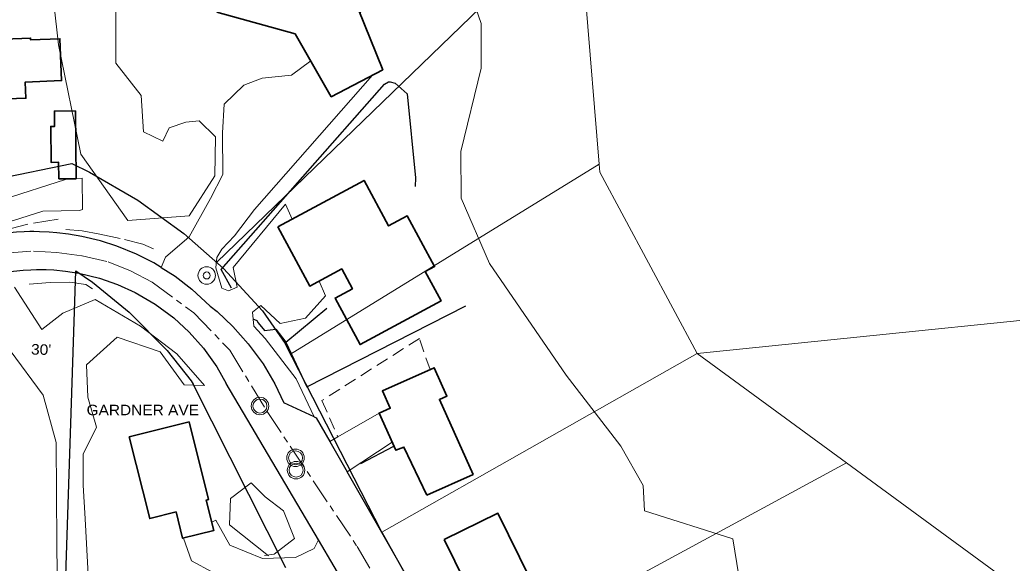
# Model space of a CAD drawing. Extents: x -861682 to -858969, y -1797841 to -1795153.
# Drawn here: x -860350 to -859783, y -1795814 to -1795504 of the extents above; entities that cross this region are included whole.
import ezdxf

# ---------------------------------------------------------------- set-up
doc = ezdxf.new("R2010")
doc.units = 0
doc.header["$LTSCALE"] = 2.4
for name, pattern in [('DOT_DASHED', [7.7, 5, -1.2, 0.3, -1.2]), ('LONG_DASH_SHORT_DASH', [9.9, 6, -1.2, 1.5, -1.2]), ('LONG_DASHED', [7.5, 6, -1.5]), ('MEDIUM_DASHED', [4.5, 3, -1.5])]:
    doc.linetypes.add(name, pattern=pattern)
for name, color, linetype, lineweight in [('10', 7, 'Continuous', 25), ('11', 7, 'Continuous', 13), ('12', 7, 'Continuous', 35), ('14', 7, 'Continuous', 25), ('18', 7, 'Continuous', 13), ('30', 7, 'Continuous', 13), ('31', 7, 'Continuous', 13), ('32', 7, 'LONG_DASH_SHORT_DASH', 13), ('36', 7, 'Continuous', 13), ('42', 7, 'Continuous', 25), ('46', 7, 'Continuous', 13), ('52', 7, 'LONG_DASHED', 13), ('63', 7, 'DOT_DASHED', 13)]:
    doc.layers.add(name, color=color, linetype=linetype, lineweight=lineweight)
doc.layers.add('43', color=7, linetype='Continuous')

msp = doc.modelspace()

# ---------------------------------------------------------------- linework, layer by layer
at = {"layer": '10'}
for p, q in [((-860179.156, -1795800.905), (-860231.882, -1795711.519)), ((-860181.698, -1795730.568), (-860198.942, -1795722.572)), ((-860172.735, -1795744.654), (-860162.861, -1795761.969))]:
    msp.add_line(p, q, dxfattribs=at)
for points in [[(-860269.159, -1795645.097), (-860273.302, -1795642.507), (-860283.128, -1795637.523), (-860294.347, -1795632.943), (-860303.791, -1795629.921), (-860314.504, -1795627.348), (-860322.106, -1795626.047), (-860328.671, -1795625.263), (-860333.065, -1795624.911), (-860338.569, -1795624.664), (-860341.875, -1795624.619), (-860344.079, -1795624.631), (-860347.383, -1795624.715), (-860351.785, -1795624.946), (-860357.274, -1795625.428), (-860364.036, -1795626.319), (-860368.961, -1795627.179)], [(-860375.595, -1795652.285), (-860370.813, -1795650.823), (-860360.031, -1795648.305), (-860353.5, -1795647.281), (-860348.02, -1795646.706), (-860343.621, -1795646.428), (-860340.317, -1795646.326), (-860338.113, -1795646.309), (-860334.807, -1795646.36), (-860330.405, -1795646.57), (-860323.823, -1795647.189), (-860316.201, -1795648.37), (-860304.422, -1795651.213), (-860294.014, -1795654.821), (-860283.982, -1795659.373), (-860272.561, -1795666.026), (-860261.946, -1795673.9), (-860253.033, -1795682.108), (-860244.998, -1795691.178), (-860237.331, -1795701.944), (-860231.882, -1795711.519)], [(-860269.159, -1795645.097), (-860261.161, -1795650.1), (-860251.532, -1795657.457), (-860241.013, -1795667.175)], [(-860241.013, -1795667.175), (-860237.163, -1795670.364), (-860228.133, -1795678.826), (-860219.339, -1795688.696), (-860210.89, -1795700.258), (-860204.159, -1795711.635), (-860198.942, -1795722.572)], [(-860181.698, -1795730.568), (-860180.436, -1795731.154), (-860172.735, -1795744.654)], [(-860099.377, -1795873.799), (-860101.725, -1795869.17), (-860162.861, -1795761.969)], [(-860092.401, -1795947.984), (-860152.258, -1795846.506), (-860179.156, -1795800.905)]]:
    msp.add_lwpolyline(points, dxfattribs=at)
at = {"layer": '11'}
for p, q in [((-860144.512, -1795728.418), (-860168.055, -1795741.962)), ((-860168.055, -1795741.962), (-860172.735, -1795744.654)), ((-860137.122, -1795744.935), (-860162.861, -1795761.969))]:
    msp.add_line(p, q, dxfattribs=at)
for points in [[(-860183.637, -1795526.981), (-860194.672, -1795535.155), (-860211.433, -1795536.955), (-860221.796, -1795540.826), (-860233.043, -1795551.794), (-860234.081, -1795568.108), (-860233.873, -1795591.972), (-860240.841, -1795605.738), (-860253.174, -1795627.585), (-860266.541, -1795639.28), (-860269.159, -1795645.097)], [(-860394.54, -1795535.544), (-860395.83, -1795553.928), (-860400.58, -1795578.308), (-860405.886, -1795593.004), (-860411.348, -1795616.918), (-860410.349, -1795623.053), (-860402.563, -1795621.803), (-860384.914, -1795613.379), (-860359.456, -1795606.304), (-860323.875, -1795594.887), (-860314.194, -1795594.093), (-860314.037, -1795612.05), (-860315.687, -1795612.537), (-860336.714, -1795612.957), (-860353.444, -1795618.301), (-860384.56, -1795626.844), (-860393.031, -1795630.935), (-860395.171, -1795632.712)], [(-860148.384, -1795535.187), (-860215.74, -1795611.898), (-860227.186, -1795627.121), (-860234.444, -1795634.746), (-860237.238, -1795639.496), (-860237.896, -1795645.409), (-860234.487, -1795656.958), (-860230.692, -1795658.579), (-860225.748, -1795656.409), (-860227.974, -1795645.086), (-860198.044, -1795608.908), (-860194.273, -1795617.548)], [(-860178.833, -1795652.933), (-860175.138, -1795661.402), (-860186.606, -1795674.026), (-860200.992, -1795677.223), (-860212.188, -1795666.924), (-860216.88, -1795670.745), (-860216.101, -1795678.772), (-860209.66, -1795685.805), (-860191.973, -1795708.807), (-860181.698, -1795730.568)], [(-860240.145, -1795790.707), (-860237.818, -1795789.547), (-860229.895, -1795803.892), (-860211.161, -1795811.526), (-860192.263, -1795810.888), (-860181.674, -1795805.833), (-860179.156, -1795800.905)], [(-860256.318, -1795799.851), (-860251.792, -1795812.826), (-860227.813, -1795825.849), (-860191.874, -1795828.371), (-860178.642, -1795828.255), (-860178.537, -1795840.305), (-860175.518, -1795861.309), (-860167.817, -1795877.31), (-860166.047, -1795890.527), (-860168.708, -1795899.351)]]:
    msp.add_lwpolyline(points, dxfattribs=at)
at = {"layer": '11', "linetype": 'MEDIUM_DASHED'}
msp.add_lwpolyline([(-860115.422, -1795703.526), (-860121.523, -1795685.743), (-860177.215, -1795721.201), (-860168.055, -1795741.962)], dxfattribs=at)
at = {"layer": '12'}
for points in [[(-860237.284, -1795499.136), (-860192.516, -1795511.505), (-860171.88, -1795547.478), (-860142.478, -1795532.098), (-860156.487, -1795497.249), (-860155.287, -1795499.365), (-860149.778, -1795480.886), (-860153.355, -1795477.136), (-860151.301, -1795468.848), (-860192.025, -1795459.516), (-860194.987, -1795472.065), (-860226.256, -1795463.123)], [(-860424.337, -1795536.689), (-860368.59, -1795534.548), (-860368.028, -1795549.18), (-860346.45, -1795548.351), (-860346.806, -1795539.091), (-860326.014, -1795538.292), (-860326.934, -1795514.356), (-860343.748, -1795515.002), (-860343.787, -1795513.998), (-860389.128, -1795515.759), (-860389.354, -1795509.933), (-860425.32, -1795511.328)], [(-860327.66, -1795594.446), (-860327.743, -1795584.995), (-860331.996, -1795585.032), (-860332.175, -1795564.476), (-860330.049, -1795564.457), (-860330.127, -1795555.715), (-860318.075, -1795555.607), (-860317.728, -1795594.357)], [(-860202.42, -1795621.941), (-860184.166, -1795655.808), (-860165.894, -1795645.959), (-860159.785, -1795657.292), (-860169.713, -1795662.644), (-860155.407, -1795689.181), (-860109.132, -1795664.234), (-860118.162, -1795647.484), (-860112.832, -1795644.61), (-860128.46, -1795615.627), (-860139.109, -1795621.369), (-860153.132, -1795595.363)], [(-860117.197, -1795775.259), (-860130.312, -1795747.806), (-860135.026, -1795749.62), (-860144.512, -1795728.418), (-860138.188, -1795725.589), (-860142.616, -1795715.691), (-860113.044, -1795702.462), (-860105.813, -1795718.627), (-860110.072, -1795720.532), (-860090.862, -1795763.479)], [(-860287.383, -1795742.011), (-860275.633, -1795788.696), (-860260.618, -1795784.917), (-860256.827, -1795799.979), (-860238.944, -1795795.478), (-860243.319, -1795778.095), (-860241.997, -1795777.762), (-860253.172, -1795733.394)], [(-860107.286, -1795800.692), (-860082.748, -1795850.573), (-860056.867, -1795837.841), (-860057.859, -1795835.824), (-860052.695, -1795833.284), (-860057.75, -1795823.007), (-860058.178, -1795823.217), (-860076.614, -1795785.643)]]:
    msp.add_lwpolyline(points, close=True, dxfattribs=at)
at = {"layer": '14'}
for p, q in [((-860197.828, -1795687.827), (-860174.367, -1795668.483)), ((-860154.925, -1795757.159), (-860136.025, -1795747.387))]:
    msp.add_line(p, q, dxfattribs=at)
for points in [[(-860228.816, -1795656.908), (-860234.816, -1795646.327), (-860141.46, -1795540.36), (-860139.11, -1795538.921), (-860138.165, -1795538.913), (-860135.321, -1795539.834), (-860128.415, -1795545.917), (-860123.743, -1795593.844), (-860123.936, -1795598.808)], [(-860197.828, -1795687.827), (-860185.853, -1795713.451), (-860094.985, -1795667.08)], [(-860216.658, -1795674.515), (-860214.477, -1795675.449), (-860213.681, -1795676.805), (-860210.016, -1795681.157), (-860203.489, -1795680.47), (-860197.828, -1795687.827)]]:
    msp.add_lwpolyline(points, dxfattribs=at)
at = {"layer": '18'}
for points in [[(-859848.857, -1796143.423), (-859830.375, -1796068.119), (-859815.416, -1795968.272), (-859832.749, -1795958.736), (-859873.693, -1796005.407), (-859912.844, -1796013.783), (-859925.323, -1795991.917), (-859900.969, -1795966.657), (-859899.258, -1795946.084), (-859926.809, -1795930.021), (-859932.369, -1795861.544), (-859942.357, -1795800.194), (-859992.827, -1795784.331), (-859993.663, -1795769.689), (-860006.382, -1795747.353), (-860037.691, -1795706.748), (-860081.491, -1795642.86), (-860097.65, -1795605.431), (-860097.883, -1795578.733), (-860086.247, -1795531.136), (-860086.234, -1795505.617), (-860108.054, -1795442.246)], [(-860352.876, -1795656.337), (-860337.305, -1795680.54), (-860325.336, -1795671.22), (-860306.736, -1795663.496), (-860280.848, -1795678.629), (-860260.151, -1795694.516), (-860244.398, -1795712.573), (-860255.98, -1795712.201), (-860269.613, -1795693.417), (-860294.262, -1795684.889), (-860311.844, -1795700.875), (-860310.974, -1795719.298), (-860306.098, -1795736.505), (-860313.761, -1795751.931), (-860313.606, -1795769.652), (-860312.494, -1795788.782), (-860310.798, -1795820.667)], [(-860328.225, -1795854.373), (-860328.673, -1795803.101), (-860329.179, -1795745.213), (-860336.505, -1795718.104), (-860355.396, -1795692.512)], [(-860207.726, -1795809.989), (-860229.996, -1795792.315), (-860229.419, -1795777.187), (-860217.682, -1795768.341), (-860209.578, -1795776.305), (-860199.112, -1795784.247), (-860192.83, -1795800.024), (-860204.566, -1795809.106), (-860210.01, -1795809.717)]]:
    msp.add_lwpolyline(points, dxfattribs=at)
msp.add_lwpolyline([(-860238.078, -1795570.504), (-860238.356, -1795592.718), (-860253.044, -1795615.531), (-860288.228, -1795618.202), (-860315.024, -1795580.392), (-860327.857, -1795517.886), (-860330.428, -1795494.043), (-860316.821, -1795482.818), (-860295.049, -1795486.645), (-860295.093, -1795508.621), (-860294.922, -1795528.232), (-860280.582, -1795546.774), (-860279.219, -1795567.556), (-860268.066, -1795572.893), (-860264.588, -1795565.301), (-860254.928, -1795562.145), (-860247.373, -1795561.37)], close=True, dxfattribs=at)
at = {"layer": '30'}
for p, q in [((-860045.907, -1795258.409), (-860018.74, -1795586.017)), ((-860237.448, -1795642.208), (-860030.662, -1795442.252)), ((-860195.131, -1795694.686), (-860018.74, -1795586.017)), ((-859962.746, -1795694.289), (-860142.962, -1795796.48)), ((-859877.343, -1795756.894), (-860098.4, -1795876.369)), ((-859790.315, -1795820.662), (-859877.343, -1795756.894))]:
    msp.add_line(p, q, dxfattribs=at)
for points in [[(-859962.746, -1795694.289), (-860018.361, -1795590.581), (-860018.74, -1795586.017)], [(-859668.412, -1795664.234), (-859962.746, -1795694.289), (-859877.343, -1795756.894)]]:
    msp.add_lwpolyline(points, dxfattribs=at)
at = {"layer": '31'}
for radius in [5, 2]:
    msp.add_circle((-860243.057, -1795649.707), radius, dxfattribs=at)
at = {"layer": '32'}
for points in [[(-861635.972, -1796031.868), (-861610.028, -1796010.347), (-861588.712, -1795995.544), (-861565.619, -1795981.925), (-861538.381, -1795968.898), (-861510.551, -1795957.055), (-861477.984, -1795945.213), (-861420.547, -1795924.488), (-861317.516, -1795885.408), (-861160.601, -1795826.787), (-861110.862, -1795807.247), (-861056.978, -1795788.298), (-861002.502, -1795772.311), (-860944.474, -1795756.916), (-860841.147, -1795735.302), (-860618.21, -1795690.893), (-860377.808, -1795641.449), (-860358.046, -1795636.933), (-860342.059, -1795635.749), (-860328.736, -1795636.637), (-860314.229, -1795638.413), (-860299.425, -1795641.966), (-860286.694, -1795646.999), (-860274.26, -1795653.513)], [(-860274.26, -1795653.513), (-860250.487, -1795671.004), (-860229.924, -1795692.424), (-860208.503, -1795727.553), (-860157.095, -1795804.667), (-860105.686, -1795892.062), (-860073.984, -1795950.325), (-860046.566, -1796011.159), (-860031.143, -1796049.715), (-860017.434, -1796100.268), (-860013.15, -1796140.538), (-860014.007, -1796179.951), (-860021.718, -1796250.638), (-860037.649, -1796318.494)]]:
    msp.add_lwpolyline(points, dxfattribs=at)
at = {"layer": '36'}
for centre, radius in [((-860212.632, -1795724.346), 5), ((-860212.632, -1795724.346), 4), ((-860192.288, -1795753.942), 5), ((-860192.288, -1795753.942), 4), ((-860191.99, -1795761.028), 5), ((-860191.99, -1795761.028), 4)]:
    msp.add_circle(centre, radius, dxfattribs=at)
at = {"layer": '42'}
for p, q in [((-860511.736, -1795625.621), (-860320.225, -1795585.642)), ((-860326.268, -1795901.28), (-860317.813, -1795647.116)), ((-860142.962, -1795796.48), (-860198.185, -1795688.55)), ((-860197.805, -1795816.843), (-860250.84, -1795711.923)), ((-860142.962, -1795796.48), (-860098.4, -1795876.369))]:
    msp.add_line(p, q, dxfattribs=at)
for points in [[(-860320.225, -1795585.642), (-860310.157, -1795590.553), (-860282.482, -1795606.56), (-860256.198, -1795625.626), (-860233.413, -1795645.776), (-860211.147, -1795669.852), (-860198.185, -1795688.55)], [(-860317.813, -1795647.116), (-860308.443, -1795653.597), (-860287.398, -1795670.611), (-860265.582, -1795692.538), (-860251.977, -1795709.961), (-860250.84, -1795711.923)]]:
    msp.add_lwpolyline(points, dxfattribs=at)
at = {"layer": '52'}
msp.add_lwpolyline([(-860327.93, -1795617.605), (-860345.392, -1795620.357), (-860372.975, -1795627.688)], dxfattribs=at)
at = {"layer": '63'}
for points in [[(-860323.626, -1795623.475), (-860314.169, -1795624.101), (-860304.226, -1795626.141), (-860290.023, -1795629.088), (-860279.602, -1795631.833), (-860273.436, -1795634.378)], [(-860308.443, -1795657.368), (-860312.246, -1795654.802), (-860321.237, -1795653.463), (-860332.577, -1795653.799), (-860346.981, -1795654.87)]]:
    msp.add_lwpolyline(points, dxfattribs=at)

# ---------------------------------------------------------------- texts
at = {"layer": '43', "width": 1.1}
msp.add_text("30'", height=6, rotation=358.413, dxfattribs=at).set_placement((-860343.525, -1795694.866))
at = {"layer": '46', "width": 1.1}
msp.add_text('GARDNER AVE', height=6, dxfattribs=at).set_placement((-860311.731, -1795729.619))

doc.saveas('drawing.dxf')
